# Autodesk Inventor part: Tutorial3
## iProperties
Shininess: 77.0
Length Units: 11269
Angle Units: 11279
Time Units: 11290
Mass Units: 11283
Length Display Precision: 3
Angle Display Precision: 2
Created: 2001-12
Part Number: Tutorial3
Document SubType Name: Modeling
Designer: Renu Muthoo
Density: 1 g/cm^3
Density: 0.0
Volumn: 0.0
Area: 0.0
PropertySet Name: Model Information
Control State: 0
Master: False
Checked Out: False
Author: Renu Muthoo
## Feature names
1. Extrusion1
2. Extrusion2
3. Hole4
4. Circular Pattern3
5. Extrusion3
6. Hole5
7. Circular Pattern4
8. Hole6
